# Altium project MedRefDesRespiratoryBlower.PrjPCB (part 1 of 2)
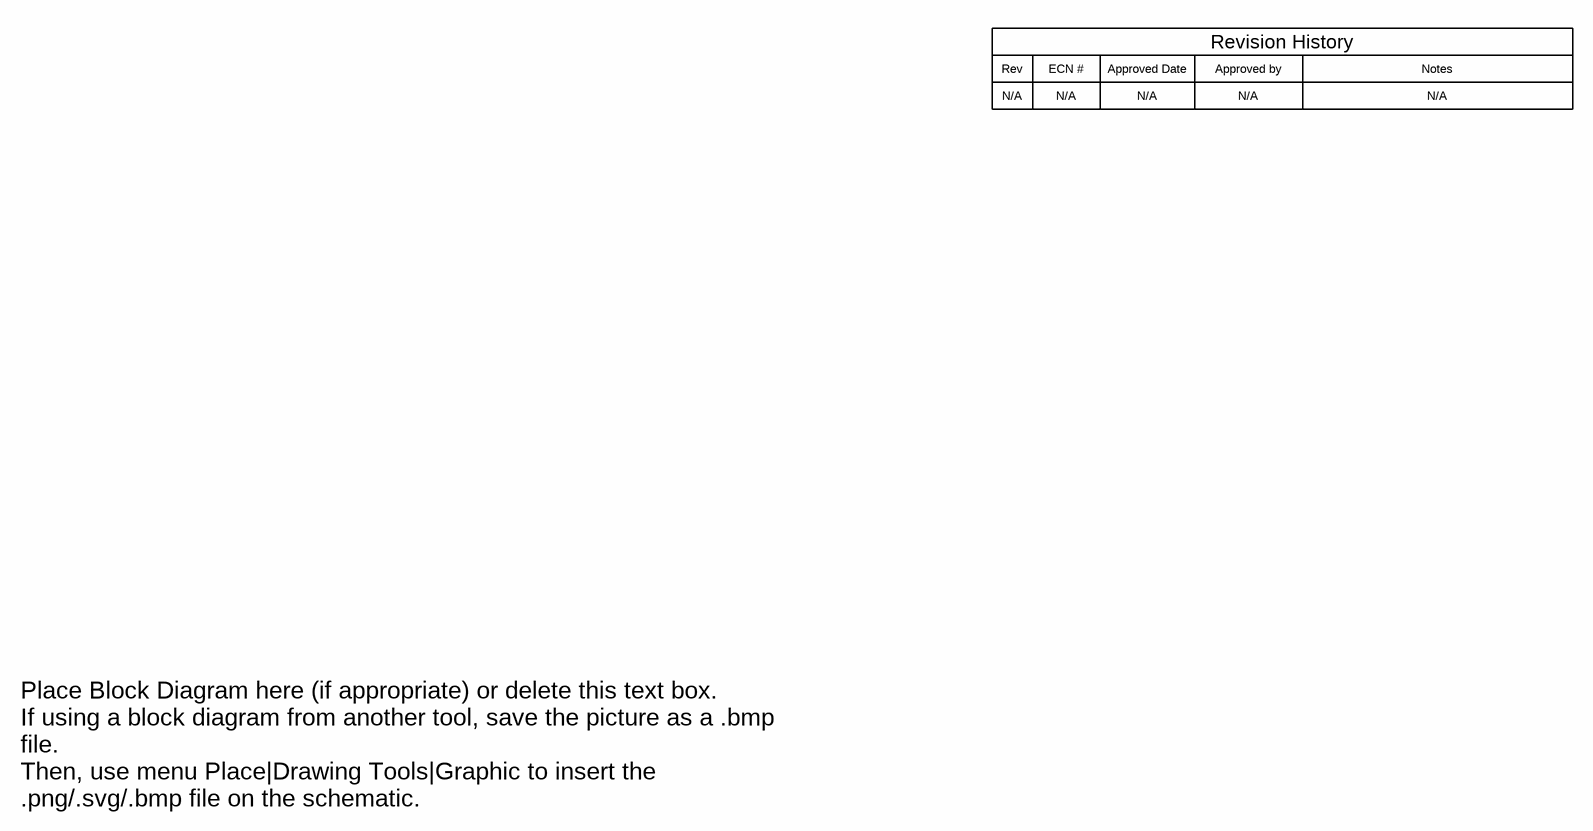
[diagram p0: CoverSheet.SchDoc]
TID: N/A; TechSupport: http://www.ti.com/support; SCH_Rev: E2; PRJ_Title: Change in menu Project|Project Options|Parameters; PRJ_Number: TIDA-010072; PRJ_Engineer: Kelvin Le; PRJ_Customer: Public Release; PCB_Rev: E2; CopyrightYear: 2020
6 sheets, 261 parts. Net scope: global (net labels, ports and power ports of the same name join across sheets).
Board file: Blower and Valve Board.PcbDoc
Sheets:
  CoverSheet.SchDoc
  Hardware.SchDoc
  BLDC Motor Driver and TMP Sensors.SchDoc
  MCU and Connectors.SchDoc
  Power Tree.SchDoc
  Valve Drivers and Fault Indicators.SchDoc

## Sheet CoverSheet.SchDoc
size 431 x 279 mm; Date: Not shown in title block; ApprovedBy: Not shown in title block; CheckedBy: Not shown in title block; Author: Not shown in title block; CompanyName: Not shown in title block; Engineer: Not shown in title block; Organization: Not shown in title block; Address1: Not shown in title block; Address2: Not shown in title block; Address3: Not shown in title block; Address4: Not shown in title block; DocumentNumber: 1; Revision: Use project parameter SCH_Rev; SheetNumber: 1; SheetTotal: 6; PageSetup: Record=PageOptions¦CenterHorizontal=True¦CenterVertical=True¦PrintScale=1.00¦XCorrection=1.00¦YCorrection=1.00¦PrintKind=0¦BorderSize=5000000¦LeftOffset=0¦BottomOffset=0¦Orientation=2¦PaperLength=1000¦PaperWidth=1000¦Scale=100¦PaperSource=15¦PrintQuality=600¦MediaType=1¦DitherType=10¦PaperKind=Letter¦PrintScaleMode=1

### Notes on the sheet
- Rev
- N/A
- ECN #
- Approved Date
- Approved by
- Revision History
- Notes
- Place Block Diagram here (if appropriate) or delete this text box.
  If using a block diagram from another tool, save the picture as a .bmp file.
  Then, use menu Place|Drawing Tools|Graphic to insert the .png/.svg/.bmp file on the schematic.

## Sheet Hardware.SchDoc
size 431 x 279 mm; Date: Not shown in title block; ApprovedBy: Not shown in title block; CheckedBy: Not shown in title block; Author: Not shown in title block; CompanyName: Not shown in title block; Engineer: Not shown in title block; Organization: Not shown in title block; Address1: Not shown in title block; Address2: Not shown in title block; Address3: Not shown in title block; Address4: Not shown in title block; DocumentNumber: 2; Revision: Use project parameter SCH_Rev; SheetNumber: 2; SheetTotal: 6; PageSetup: Record=PageOptions¦CenterHorizontal=True¦CenterVertical=True¦PrintScale=1.00¦XCorrection=1.00¦YCorrection=1.00¦PrintKind=0¦BorderSize=5000000¦LeftOffset=0¦BottomOffset=0¦Orientation=2¦PaperLength=1000¦PaperWidth=1000¦Scale=100¦PaperSource=15¦PrintQuality=600¦MediaType=1¦DitherType=10¦PaperKind=Letter¦PrintScaleMode=1
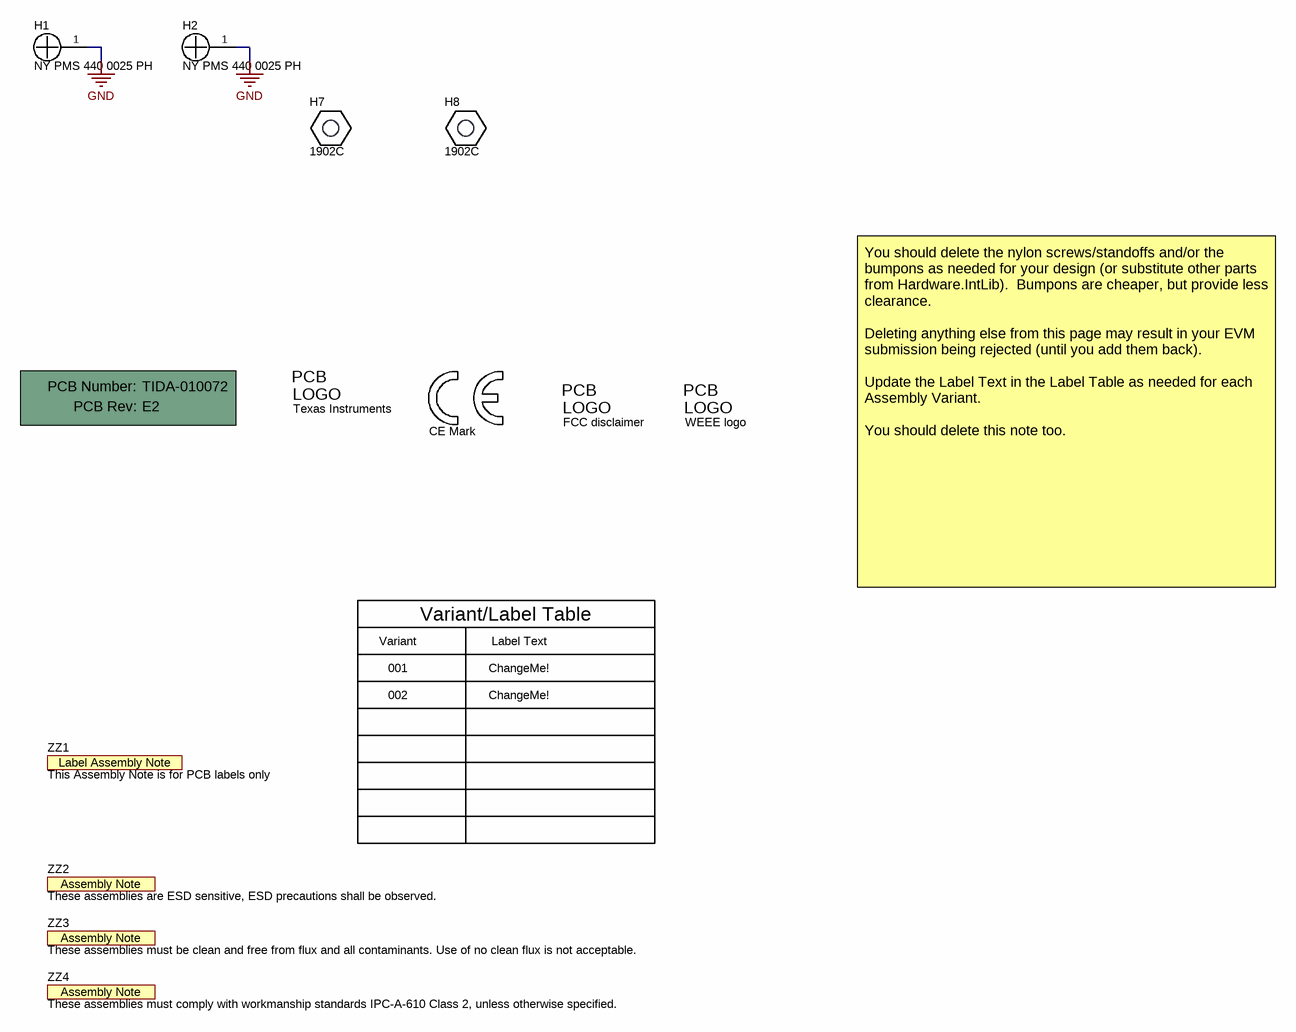
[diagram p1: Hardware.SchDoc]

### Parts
!PCB1  Printed Circuit Board  (value not drawn)  (mechanical)
H1  NY PMS 440 0025 PH  [NY PMS 440 0025 PH]
H2  NY PMS 440 0025 PH  [NY PMS 440 0025 PH]
H7  1902C  [Keystone_1902C]
H8  1902C  [Keystone_1902C]
Logo1  CE Mark  [CE_Mark_5mm]  (no BOM)
Logo2  Texas Instruments  [TI_Stacked_Overlay_Small]  (no BOM)
Logo3  FCC disclaimer  [FCC_disclaimer_stacked]  (no BOM)
Logo4  WEEE logo  [WEEE_Minimum]  (no BOM)
ZZ1  This Assembly Note is for PCB labels only  [AssemblyNoteLabel]  (no BOM)
ZZ2  These assemblies are ESD sensitive, ESD precautions shall be observed.  [AssemblyNote]  (no BOM)
ZZ3  These assemblies must be clean and free from flux and all contaminants. Use of no clean flux is not acceptable.  [AssemblyNote]  (no BOM)
ZZ4  These assemblies must comply with workmanship standards IPC-A-610 Class 2, unless otherwise specified.  [AssemblyNote]  (no BOM)

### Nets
GND: H1.1 H2.1

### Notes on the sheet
- Variant
- Variant/Label Table
- Label Text
- You should delete the nylon screws/standoffs and/or the bumpons as needed for your design (or substitute other parts from Hardware.IntLib).  Bumpons are cheaper, but provide less clearance.
  Deleting anything else from this page may result in your EVM submission being rejected (until you add them back).
  Update the Label Text in the Label Table as needed for each Assembly Variant.
  You should delete this note too.
- 001
- 002
- ChangeMe!

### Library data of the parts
!PCB1 = CMP-0003618-2: Manufacturer: Any; PartNumber: TIDA-010072
H1 H2 = CMP-0003617-1: Machine Screw, Round, #4-40 x 1/4, Nylon, Philips panhead; Manufacturer: B&F Fastener Supply; CompType: Hardware
H7 H8 = CMP-0003610-1: Standoff, Hex, 0.5"L #4-40 Nylon; Manufacturer: Keystone; CompType: Hardware
Logo1 = CMP-0074844-1: SymbolCreator: a0412235
Logo2 = CMP-0074838-1: Texas Instrument Corporate Signature; SymbolCreator: a0412235; Lib Reference: TI_Logo; Library Reference: Logo
Logo3 = CMP-0074847-1: FCC_disclaimer; Library Reference: Logo
Logo4 = CMP-0074769-1
ZZ1 = CMP-0003616-3
ZZ2 = CMP-0077236-1
ZZ3 = CMP-0077237-1
ZZ4 = CMP-0077238-1

## Sheet BLDC Motor Driver and TMP Sensors.SchDoc
size 431 x 279 mm; Date: Not shown in title block; ApprovedBy: Not shown in title block; CheckedBy: Not shown in title block; Author: Not shown in title block; CompanyName: Not shown in title block; Engineer: Not shown in title block; Organization: Not shown in title block; Address1: Not shown in title block; Address2: Not shown in title block; Address3: Not shown in title block; Address4: Not shown in title block; DocumentNumber: 2; Revision: Use project parameter SCH_Rev; SheetNumber: 2; SheetTotal: 3; PageSetup: Record=PageOptions¦CenterHorizontal=True¦CenterVertical=True¦PrintScale=1.00¦XCorrection=1.00¦YCorrection=1.00¦PrintKind=0¦BorderSize=5000000¦LeftOffset=0¦BottomOffset=0¦Orientation=2¦PaperLength=1000¦PaperWidth=1000¦Scale=100¦PaperSource=15¦PrintQuality=600¦MediaType=1¦DitherType=10¦PaperKind=Letter¦PrintScaleMode=1
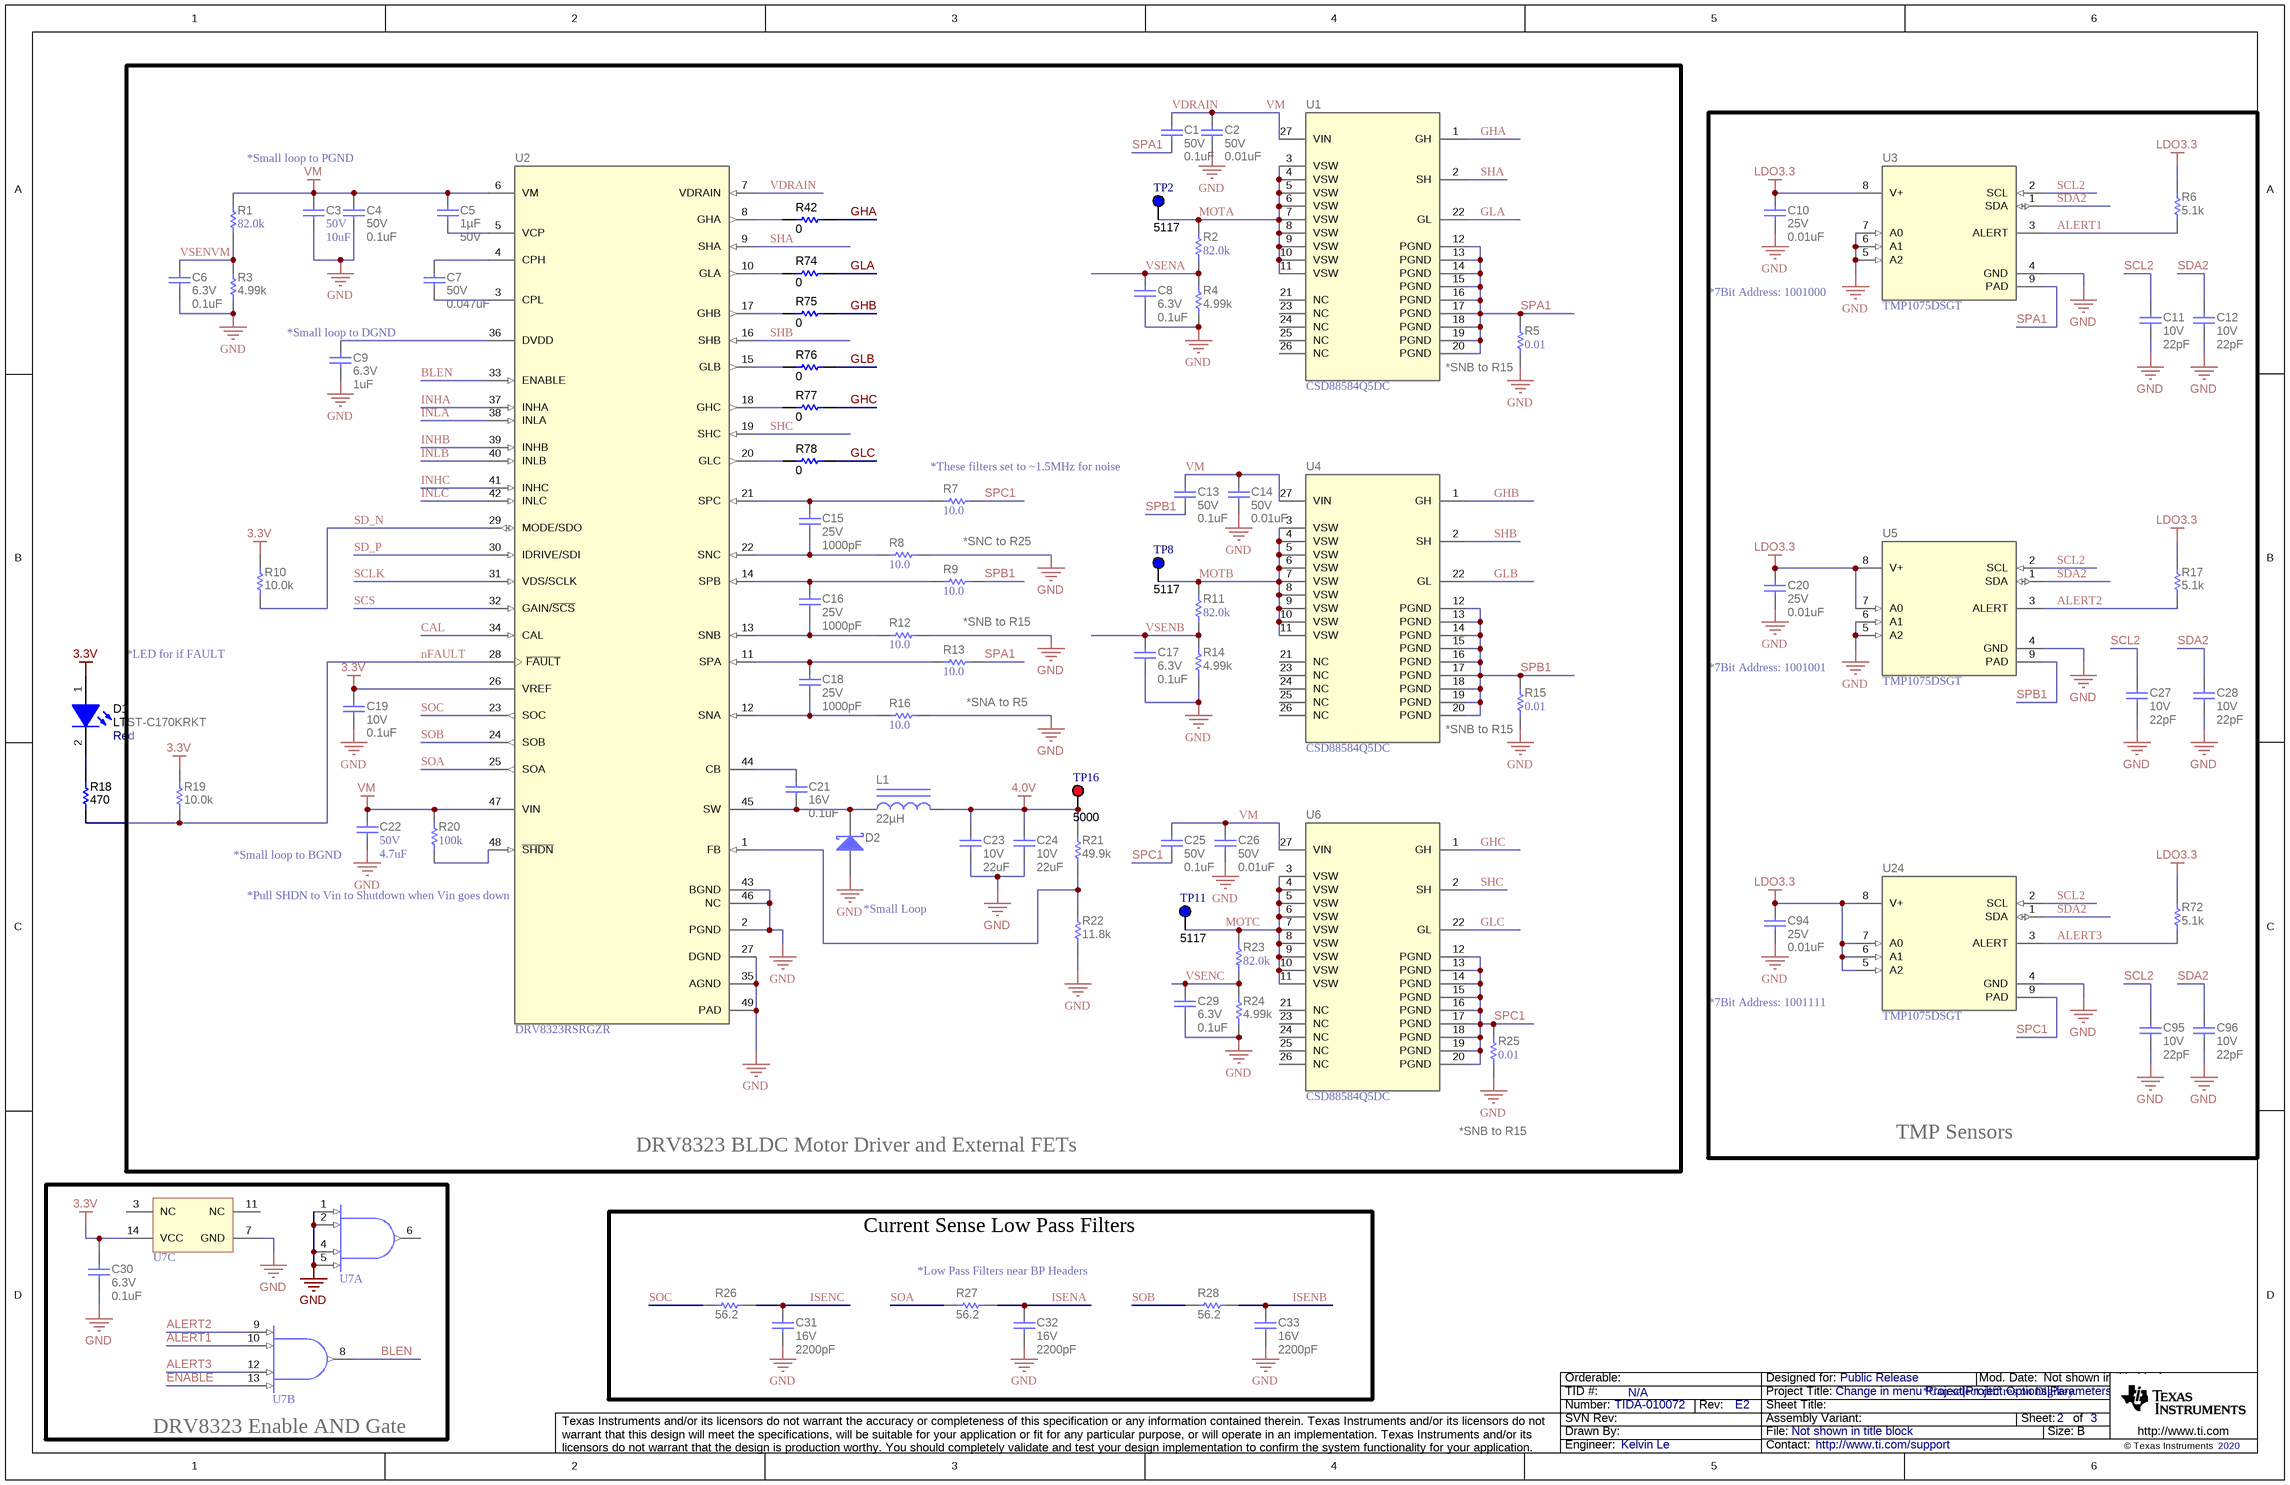
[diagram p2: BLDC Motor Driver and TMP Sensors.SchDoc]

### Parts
C1  VDC_V: 50V  ValueDisplayed: 0.1uF  [0402]  (hidden comment: C1005X7R1H104K050BB)
C2  VDC_V: 50V  ValueDisplayed: 0.01uF  [0402]  (hidden comment: GRM155R71H103KA88D)
C3  VDC_V: 50V  ValueDisplayed: 10uF  [1206_180]  (hidden comment: CL31B106KBHNNNE)
C4  VDC_V: 50V  ValueDisplayed: 0.1uF  [0402]  (hidden comment: C1005X7R1H104K050BB)
C5  Cap_F: 1µF  VDC_V: 50V  [0603]  (hidden comment: UMK107AB7105KA-T)
C6  VDC_V: 6.3V  ValueDisplayed: 0.1uF  [0402]  (hidden comment: 885012105001)
C7  VDC_V: 50V  ValueDisplayed: 0.047uF  [0402]  (hidden comment: C1005X7R1H473K050BB)
C8  VDC_V: 6.3V  ValueDisplayed: 0.1uF  [0402]  (hidden comment: 885012105001)
C9  VDC_V: 6.3V  ValueDisplayed: 1uF  [0402]  (hidden comment: GRM155R70J105MA12D)
C10  VDC_V: 25V  ValueDisplayed: 0.01uF  [0402]  (hidden comment: GRM155R71E103KA01D)
C11  VDC_V: 10V  ValueDisplayed: 22pF  [0402]  (hidden comment: 885012005009)
C12  VDC_V: 10V  ValueDisplayed: 22pF  [0402]  (hidden comment: 885012005009)
C13  VDC_V: 50V  ValueDisplayed: 0.1uF  [0402]  (hidden comment: C1005X7R1H104K050BB)
C14  VDC_V: 50V  ValueDisplayed: 0.01uF  [0402]  (hidden comment: GRM155R71H103KA88D)
C15  VDC_V: 25V  ValueDisplayed: 1000pF  [0402]  (hidden comment: GRM155R61E102KA01D)
C16  VDC_V: 25V  ValueDisplayed: 1000pF  [0402]  (hidden comment: GRM155R61E102KA01D)
C17  VDC_V: 6.3V  ValueDisplayed: 0.1uF  [0402]  (hidden comment: 885012105001)
C18  VDC_V: 25V  ValueDisplayed: 1000pF  [0402]  (hidden comment: GRM155R61E102KA01D)
C19  VDC_V: 10V  ValueDisplayed: 0.1uF  [0402]  (hidden comment: 885012105010)
C20  VDC_V: 25V  ValueDisplayed: 0.01uF  [0402]  (hidden comment: GRM155R71E103KA01D)
C21  VDC_V: 16V  ValueDisplayed: 0.1uF  [0402_065]  (hidden comment: 160R07X104KV4T)
C22  VDC_V: 50V  ValueDisplayed: 4.7uF  [0805_HV]  (hidden comment: C2012X5R1H475K125AB)
C23  VDC_V: 10V  ValueDisplayed: 22uF  [0603]  (hidden comment: C1608X5R1A226M080AC)
C24  VDC_V: 10V  ValueDisplayed: 22uF  [0603]  (hidden comment: C1608X5R1A226M080AC)
C25  VDC_V: 50V  ValueDisplayed: 0.1uF  [0402]  (hidden comment: C1005X7R1H104K050BB)
C26  VDC_V: 50V  ValueDisplayed: 0.01uF  [0402]  (hidden comment: GRM155R71H103KA88D)
C27  VDC_V: 10V  ValueDisplayed: 22pF  [0402]  (hidden comment: 885012005009)
C28  VDC_V: 10V  ValueDisplayed: 22pF  [0402]  (hidden comment: 885012005009)
C29  VDC_V: 6.3V  ValueDisplayed: 0.1uF  [0402]  (hidden comment: 885012105001)
C30  VDC_V: 6.3V  ValueDisplayed: 0.1uF  [0402]  (hidden comment: 885012105001)
C31  VDC_V: 16V  ValueDisplayed: 2200pF  [0402]  (hidden comment: GRM155R61C222KA01D)
C32  VDC_V: 16V  ValueDisplayed: 2200pF  [0402]  (hidden comment: GRM155R61C222KA01D)
C33  VDC_V: 16V  ValueDisplayed: 2200pF  [0402]  (hidden comment: GRM155R61C222KA01D)
C94  VDC_V: 25V  ValueDisplayed: 0.01uF  [0402]  (hidden comment: GRM155R71E103KA01D)
C95  VDC_V: 10V  ValueDisplayed: 22pF  [0402]  (hidden comment: 885012005009)
C96  VDC_V: 10V  ValueDisplayed: 22pF  [0402]  (hidden comment: 885012005009)
D1  LTST-C170KRKT  value Red  [LED_LTST-C170_Red]
D2  PMEG6010CEH,115  [SOD-123F]  (value not drawn)
L1  ValueDisplayed: 22µH  [WE-MAPI_4020]  (hidden comment: 74438356220)
R1  ValueDisplayed: 82.0k  [0402]  (hidden comment: RC0402FR-0782KL)
R2  ValueDisplayed: 82.0k  [0402]  (hidden comment: RC0402FR-0782KL)
R3  ValueDisplayed: 4.99k  [0402]  (hidden comment: CRCW04024K99FKED)
R4  ValueDisplayed: 4.99k  [0402]  (hidden comment: CRCW04024K99FKED)
R5  ValueDisplayed: 0.01  [2512]  (hidden comment: CRA2512-FZ-R010ELF)
R6  ValueDisplayed: 5.1k  [0402]  (hidden comment: CRCW04025K10JNED)
R7  ValueDisplayed: 10.0  [0402]  (hidden comment: RK73H1ETTP10R0F)
R8  ValueDisplayed: 10.0  [0402]  (hidden comment: RK73H1ETTP10R0F)
R9  ValueDisplayed: 10.0  [0402]  (hidden comment: RK73H1ETTP10R0F)
R10  ValueDisplayed: 10.0k  [0402]  (hidden comment: CRCW040210K0FKED)
R11  ValueDisplayed: 82.0k  [0402]  (hidden comment: RC0402FR-0782KL)
R12  ValueDisplayed: 10.0  [0402]  (hidden comment: RK73H1ETTP10R0F)
R13  ValueDisplayed: 10.0  [0402]  (hidden comment: RK73H1ETTP10R0F)
R14  ValueDisplayed: 4.99k  [0402]  (hidden comment: CRCW04024K99FKED)
R15  ValueDisplayed: 0.01  [2512]  (hidden comment: CRA2512-FZ-R010ELF)
R16  ValueDisplayed: 10.0  [0402]  (hidden comment: RK73H1ETTP10R0F)
R17  ValueDisplayed: 5.1k  [0402]  (hidden comment: CRCW04025K10JNED)
R18  ValueDisplayed: 470  [0402]  (hidden comment: CRCW0402470RJNED)
R19  ValueDisplayed: 10.0k  [0402]  (hidden comment: CRCW040210K0FKED)
R20  ValueDisplayed: 100k  [0402]  (hidden comment: RMCF0402FT100K)
R21  ValueDisplayed: 49.9k  [0402]  (hidden comment: CRCW040249K9FKED)
R22  ValueDisplayed: 11.8k  [0402]  (hidden comment: CRCW040211K8FKED)
R23  ValueDisplayed: 82.0k  [0402]  (hidden comment: RC0402FR-0782KL)
R24  ValueDisplayed: 4.99k  [0402]  (hidden comment: CRCW04024K99FKED)
R25  ValueDisplayed: 0.01  [2512]  (hidden comment: CRA2512-FZ-R010ELF)
R26  ValueDisplayed: 56.2  [0402]  (hidden comment: CRCW040256R2FKED)
R27  ValueDisplayed: 56.2  [0402]  (hidden comment: CRCW040256R2FKED)
R28  ValueDisplayed: 56.2  [0402]  (hidden comment: CRCW040256R2FKED)
R42  ValueDisplayed: 0  [0402]  (hidden comment: CRCW04020000Z0EDHP)
R72  ValueDisplayed: 5.1k  [0402]  (hidden comment: CRCW04025K10JNED)
R74  ValueDisplayed: 0  [0402]  (hidden comment: CRCW04020000Z0EDHP)
R75  ValueDisplayed: 0  [0402]  (hidden comment: CRCW04020000Z0EDHP)
R76  ValueDisplayed: 0  [0402]  (hidden comment: CRCW04020000Z0EDHP)
R77  ValueDisplayed: 0  [0402]  (hidden comment: CRCW04020000Z0EDHP)
R78  ValueDisplayed: 0  [0402]  (hidden comment: CRCW04020000Z0EDHP)
TP2  5117  [Keystone5117]
TP8  5117  [Keystone5117]
TP11  5117  [Keystone5117]
TP16  5000  [Keystone5000]
U1  CSD88584Q5DC  [DMM0022A]
U2  DRV8323RSRGZR  [RGZ0048A]
U3  TMP1075DSGT  [DSG0008A]
U4  CSD88584Q5DC  [DMM0022A]
U5  TMP1075DSGT  [DSG0008A]
U6  CSD88584Q5DC  [DMM0022A]
U7  SN74HC21PW  [PW0014A_N]  (value not drawn)  (parts A,B,C of 3)
U24  TMP1075DSGT  [DSG0008A]

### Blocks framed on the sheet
DRV8323 BLDC Motor Driver and External FETs: C1-C9 C13-C19 C21-C26 C29 D2 L1 R1-R5 R7-R16 R19-R25 R42 R74-R78 TP2 TP8 TP11 TP16 U1 U2 U4 U6
TMP Sensors: C10-C12 C20 C27 C28 C94-C96 R6 R17 R72 U3 U5 U24
DRV8323 Enable AND Gate: C30 U7
Current Sense Low Pass Filters: C31-C33 R26-R28

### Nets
3.3V: C19.1 C30.1 D1.1(A) R10.2 R19.2 U2.26(VREF) U7.14(VCC)
4.0V: C23.1 C24.1 L1.2 R21.2 TP16.1
GND: C2.2 C3.2 C4.2 C6.2 C8.2 C9.2 C10.2 C11.2 C12.2 C14.2 C17.2 C19.2 C20.2 C22.2 C23.2 C24.2 C26.2 C27.2 C28.2 C29.2 C30.2 C31.2 C32.2 C33.2 C94.2 C95.2 C96.2 D2.2(A) R3.1 R4.1 R5.1 R8.1 R12.1 R14.1 R15.1 R16.1 R22.1 R24.1 R25.1 U2.2(PGND) U2.27(DGND) U2.35(AGND) U2.43(BGND) U2.46(NC) U2.49(PAD) U3.4(GND) U3.5(A2) U3.6(A1) U3.7(A0) U5.4(GND) U5.5(A2) U5.6(A1) U7.1(1A) U7.2(1B) U7.4(1C) U7.5(1D) U7.7(GND) U24.4(GND)
LDO3.3: C10.1 C20.1 C94.1 R6.2 R17.2 R72.2 U3.8(V+) U5.7(A0) U5.8(V+) U24.5(A2) U24.6(A1) U24.7(A0) U24.8(V+)
VDRAIN: C1.1 C2.1 C3.1 C4.1 C5.1 C13.1 C14.1 C22.1 C25.1 C26.1 R1.2 R20.2 U1.27(VIN) U2.6(VM) U2.7(VDRAIN) U2.47(VIN) U4.27(VIN) U6.27(VIN)  [also labelled VM]
ALERT1: R6.1 U3.3(ALERT) U7.10(2B)
ALERT2: R17.1 U5.3(ALERT) U7.9(2A)
ALERT3: R72.1 U7.12(2C) U24.3(ALERT)
BLEN: U2.33(ENABLE) U7.8(2Y)
CAL: U2.34(CAL)
ENABLE: U7.13(2D)
GHA: R42.2 U1.1(GH)
GHB: R75.2 U4.1(GH)
GHC: R77.2 U6.1(GH)
GLA: R74.2 U1.22(GL)
GLB: R76.2 U4.22(GL)
GLC: R78.2 U6.22(GL)
INHA: U2.37(INHA)
INHB: U2.39(INHB)
INHC: U2.41(INHC)
INLA: U2.38(INLA)
INLB: U2.40(INLB)
INLC: U2.42(INLC)
ISENA: C32.1 R27.2
ISENB: C33.1 R28.2
ISENC: C31.1 R26.2
MOTA: R2.2 TP2.1 U1.3(VSW) U1.4(VSW) U1.5(VSW) U1.6(VSW) U1.7(VSW) U1.8(VSW) U1.9(VSW) U1.10(VSW) U1.11(VSW)
MOTB: R11.2 TP8.1 U4.3(VSW) U4.4(VSW) U4.5(VSW) U4.6(VSW) U4.7(VSW) U4.8(VSW) U4.9(VSW) U4.10(VSW) U4.11(VSW)
MOTC: R23.2 TP11.1 U6.3(VSW) U6.4(VSW) U6.5(VSW) U6.6(VSW) U6.7(VSW) U6.8(VSW) U6.9(VSW) U6.10(VSW) U6.11(VSW)
nFAULT: R18.1 R19.1 U2.28(~{FAULT})
SCL2: C11.1 C27.1 C95.1 U3.2(SCL) U5.2(SCL) U24.2(SCL)
SCLK: U2.31(VDS/SCLK)
SCS: U2.32(GAIN/~{SCS})
SD_N: R10.1 U2.29(MODE/SDO)
SD_P: U2.30(IDRIVE/SDI)
SDA2: C12.1 C28.1 C96.1 U3.1(SDA) U5.1(SDA) U24.1(SDA)
SHA: U1.2(SH) U2.9(SHA)
SHB: U2.16(SHB) U4.2(SH)
SHC: U2.19(SHC) U6.2(SH)
SOA: R27.1 U2.25(SOA)
SOB: R28.1 U2.24(SOB)
SOC: R26.1 U2.23(SOC)
SPA1: C1.2 R5.2 R13.1 U1.12(PGND) U1.13(PGND) U1.14(PGND) U1.15(PGND) U1.16(PGND) U1.17(PGND) U1.18(PGND) U1.19(PGND) U1.20(PGND) U3.9(PAD)
SPB1: C13.2 R9.1 R15.2 U4.12(PGND) U4.13(PGND) U4.14(PGND) U4.15(PGND) U4.16(PGND) U4.17(PGND) U4.18(PGND) U4.19(PGND) U4.20(PGND) U5.9(PAD)
SPC1: C25.2 R7.1 R25.2 U6.12(PGND) U6.13(PGND) U6.14(PGND) U6.15(PGND) U6.16(PGND) U6.17(PGND) U6.18(PGND) U6.19(PGND) U6.20(PGND) U24.9(PAD)
VSENA: C8.1 R2.1 R4.2
VSENB: C17.1 R11.1 R14.2
VSENC: C29.1 R23.1 R24.2
VSENVM: C6.1 R1.1 R3.2
NetC5_2: C5.2 U2.5(VCP)
NetC7_1: C7.1 U2.4(CPH)
NetC7_2: C7.2 U2.3(CPL)
NetC9_1: C9.1 U2.36(DVDD)
NetC15_1: C15.1 R7.2 U2.21(SPC)
NetC15_2: C15.2 R8.2 U2.22(SNC)
NetC16_1: C16.1 R9.2 U2.14(SPB)
NetC16_2: C16.2 R12.2 U2.13(SNB)
NetC18_1: C18.1 R13.2 U2.11(SPA)
NetC18_2: C18.2 R16.2 U2.12(SNA)
NetC21_1: C21.1 U2.44(CB)
NetC21_2: C21.2 D2.1(K) L1.1 U2.45(SW)
NetD1_2: D1.2(K) R18.2
NetR20_1: R20.1 U2.48(~{SHDN})
NetR21_1: R21.1 R22.2 U2.1(FB)
NetR42_1: R42.1 U2.8(GHA)
NetR74_1: R74.1 U2.10(GLA)
NetR75_1: R75.1 U2.17(GHB)
NetR76_1: R76.1 U2.15(GLB)
NetR77_1: R77.1 U2.18(GHC)
NetR78_1: R78.1 U2.20(GLC)

Not connected (* = marked no-connect by the designer): U1 21(NC) 23(NC) 24(NC) 25(NC) 26(NC); U4 21(NC) 23(NC) 24(NC) 25(NC) 26(NC); U6 21(NC) 23(NC) 24(NC) 25(NC) 26(NC); U7 3(NC) 6(1Y) 11(NC)

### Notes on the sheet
- *Small loop to PGND
- (near U3) *7Bit Address: 1001000
- (near C9) *Small loop to DGND
- *SNB to R15
- *These filters set to
  .5MHz for noise
- *SNC to R25
- *LED for if FAULT
- *SNA to R5
- (near U5) *7Bit Address: 1001001
- (near C22) *Small loop to BGND
- (near U2) *Pull SHDN to Vin to Shutdown when Vin goes down
- *Small Loop
- (near U24) *7Bit Address: 1001111
- *Low Pass Filters near BP Headers
- *Can select diff res on Digikey

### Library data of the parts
C1 C4 C13 C25 = CMP-0006297-2: CAP, CERM, 0.1 uF, 50 V, +/- 10%, X7R, 0402; Manufacturer: TDK; TaMin_C: -55°C; ESR_ohm: 0.039064; Polarized: N; SizeAreaWB_mm2: 3; Value1: 0.039064 ohm; U/M: EA; Value: 0.1uF; TaMax_C: 125°C; SizeZ_mm: 0.6; SizeX_mm: 1; SizeY_mm: 0.5; Cap_F: 100nF; IRMS_A: 814.669mA; AEC Category: Q200
C2 C14 C26 = CMP-0006674-2: CAP, CERM, 0.01 uF, 50 V, +/- 10%, X7R, 0402; Manufacturer: MuRata; TaMin_C: -55°C; Polarized: N; SizeAreaWB_mm2: 3; Value1: Unknown; U/M: EA; Value: 0.01uF; TaMax_C: 125°C; SizeZ_mm: 0.6; SizeX_mm: 1; SizeY_mm: 0.5; Cap_F: 10nF; AEC Category: Q200
C3 = CMP-0008802-2: CAP, CERM, 10 uF, 50 V, +/- 10%, X7R, 1206; Manufacturer: Samsung; TaMin_C: -55°C; Polarized: N; SizeAreaWB_mm2: 10.92; Value1: Unknown; U/M: EA; Value: 10uF; TaMax_C: 125°C; SizeZ_mm: 1.8; SizeX_mm: 3.2; SizeY_mm: 1.6; Cap_Case: 1206; SizeArea_mm2: 5.12; Cap_F: 10µF; AEC Category: Q200
C5 = CMP-0007508-5: CAP, CERM, 1 uF, 50 V, +/- 10%, X7R, 0603; Manufacturer: Taiyo Yuden; TaMin_C: -55°C; Polarized: N; SizeAreaWB_mm2: 4.68; Value1: Unknown; U/M: EA; Value: 1uF; TaMax_C: 125°C; SizeZ_mm: 1; SizeX_mm: 1.6; SizeY_mm: 0.8; SizeArea_mm2: 1.28; AEC Category: Q200
C6 C8 C17 C29 C30 = CMP-0006219-2: CAP, CERM, 0.1 uF, 6.3 V, +/- 20%, X5R, 0402; Manufacturer: Wurth Elektronik; TaMin_C: -55°C; Polarized: N; SizeAreaWB_mm2: 3; Value1: Unknown; U/M: EA; Value: 0.1uF; TaMax_C: 85°C; SizeZ_mm: 0.6; SizeX_mm: 1; SizeY_mm: 0.5; Cap_F: 100nF; AEC Category: Q200
C7 = CMP-0006298-2: CAP, CERM, 0.047 uF, 50 V, +/- 10%, X7R, 0402; Manufacturer: TDK; TaMin_C: -55°C; ESR_ohm: 0.06407; Polarized: N; SizeAreaWB_mm2: 3; Value1: 0.06407 ohm; U/M: EA; SizeZ_mm: 0.6; SizeX_mm: 1; SizeY_mm: 0.5; Cap_F: 47nF; IRMS_A: 646.122mA; AEC Category: Q200; TaMax_C: 125°C
C9 = CMP-0006624-2: CAP, CERM, 1 uF, 6.3 V, +/- 20%, X7R, 0402; Manufacturer: MuRata; TaMin_C: -55°C; Polarized: N; SizeAreaWB_mm2: 3; Value1: Unknown; U/M: EA; Value: 1uF; TaMax_C: 125°C; SizeZ_mm: 0.6; SizeX_mm: 1; SizeY_mm: 0.5; Cap_F: 1µF; AEC Category: Q200
C10 C20 C94 = CMP-0006658-2: CAP, CERM, 0.01 uF, 25 V, +/- 10%, X7R, 0402; Manufacturer: MuRata; TaMin_C: -55°C; Polarized: N; SizeAreaWB_mm2: 3; Value1: Unknown; U/M: EA; Value: 0.01uF; TaMax_C: 125°C; SizeZ_mm: 0.6; SizeX_mm: 1; SizeY_mm: 0.5; Cap_F: 10nF; AEC Category: Q200
C11 C12 C27 C28 C95 C96 = CMP-0064912-2: CAP, CERM, 22 pF, 10 V,+/- 5%, C0G/NP0, 0402; Manufacturer: Wurth Elektronik; TaMin_C: -55°C; Polarized: N; SizeAreaWB_mm2: 3; Value1: Unknown; U/M: EA; Value: 22pF; TaMax_C: 125°C; SizeZ_mm: 0.6; SizeX_mm: 1; SizeY_mm: 0.5; AEC Category: Q200
C15 C16 C18 = CMP-0006606-2: CAP, CERM, 1000 pF, 25 V, +/- 10%, X5R, 0402; Manufacturer: MuRata; TaMin_C: -55°C; Polarized: N; SizeAreaWB_mm2: 3; Value1: Unknown; U/M: EA; Value: 1000pF; TaMax_C: 85°C; SizeZ_mm: 0.6; SizeX_mm: 1; SizeY_mm: 0.5; Cap_F: 1nF; AEC Category: Q200
C19 = CMP-0006221-2: CAP, CERM, 0.1 uF, 10 V, +/- 20%, X5R, 0402; Manufacturer: Wurth Elektronik; TaMin_C: -55°C; Polarized: N; SizeAreaWB_mm2: 3; Value1: Unknown; U/M: EA; Value: 0.1uF; TaMax_C: 85°C; SizeZ_mm: 0.6; SizeX_mm: 1; SizeY_mm: 0.5; Cap_F: 100nF; AEC Category: Q200
C21 = CMP-0006204-2: CAP, CERM, 0.1 uF, 16 V, +/- 10%, X5R, 0402; Manufacturer: Johanson Technology; TaMin_C: -55°C; Polarized: N; SizeAreaWB_mm2: 3; Value1: Unknown; U/M: EA; Value: 0.1uF; TaMax_C: 85°C; SizeZ_mm: 0.65; SizeX_mm: 1; SizeY_mm: 0.5; Cap_Case: 0402; Cap_F: 100nF; AEC Category: Q200
C22 = CMP-0007840-2: CAP, CERM, 4.7 uF, 50 V, +/- 10%, X5R, 0805; Manufacturer: TDK; TaMin_C: -55°C; ESR_ohm: 2.346m; Polarized: N; SizeAreaWB_mm2: 6.75; Value1: 0.002346 ohm; U/M: EA; Value: 4.7uF; TaMax_C: 85°C; SizeZ_mm: 1.45; SizeX_mm: 2; SizeY_mm: 1.25; Cap_Case: 0805; SizeArea_mm2: 2.5; Cap_F: 4.7µF; IRMS_A: 4.26021A; AEC Category: Q200
C23 C24 = CMP-0007005-5: CAP, CERM, 22 uF, 10 V, +/- 20%, X5R, 0603; Manufacturer: TDK; TaMin_C: -55°C; ESR_ohm: 3.71m; Polarized: N; SizeAreaWB_mm2: 4.68; Value1: 0.00371 ohm; U/M: EA; Value: 22uF; TaMax_C: 85°C; SizeZ_mm: 1; SizeX_mm: 1.6; SizeY_mm: 0.8; SizeArea_mm2: 1.28; Cap_F: 22µF; IRMS_A: 2.69936A; AEC Category: Q200
C31-C33 = CMP-0006592-2: CAP, CERM, 2200 pF, 16 V, +/- 10%, X5R, 0402; Manufacturer: MuRata; TaMin_C: -55°C; Polarized: N; SizeAreaWB_mm2: 3; Value1: Unknown; U/M: EA; Value: 2200pF; TaMax_C: 85°C; SizeZ_mm: 0.6; SizeX_mm: 1; SizeY_mm: 0.5; Cap_F: 2.2nF; AEC Category: Q200
D1 = CMP-0002829-3: LED, Red, SMD; Manufacturer: Lite-On; Io_A: 20mA; SizeAreaWB_mm2: 6.75; Value1: W; SizeZ_mm: 1.2; SizeX_mm: 2; SizeY_mm: 1.25; Vf_V: 2V; SizeArea_mm2: 2.5; Type: AlInGaP
D2 = CMP-0028377-2: Diode, Schottky, 60 V, 1 A, SOD-123F; Manufacturer: Nexperia; Value1: 1A; Value2: 0.57V; TJmax_C: 150°C; Green_REACh: Incomplete; Vr_V: 60V; SizeY_mm: 1.6; Vf_V: 570mV; SizeArea_mm2: 5.6; AEC Category: Q101; SizeZ_mm: 1.1; SizeX_mm: 3.5; Value: 60V; Green_Lifecycle: Not Set; SizeAreaWB_mm2: 11.7
L1 = CMP-0082329-1: Inductor, Shielded, 22 µH, 1.7 A, 0.28 ohm, SMD; Manufacturer: Wurth Elektronik; SizeAreaWB_mm2: 26.01; Irms: 1.7A @ 40C rise; SizeArea_mm2: 16.81; AEC Qualified: N; AEC Category: Q200; Value: 22uH; SizeZ_mm: 2.1; Imax_A: 1.7A; SizeY_mm: 4.1; Isat: 1.85A @ 20% inductance drop; DCR_ohm: 0.28
R1 R2 R11 R23 = CMP-0026744-1: RES, 82.0 k, 1%, 0.063 W, 0402; Manufacturer: Yageo America; Power_W: 63mW; TempCo: 100 ppm/C; Value_Code: 82k0; U/M: EA; Value: 82.0k; Res_ohm: 82k; SizeX_mm: 1; SizeY_mm: 0.5; SizeZ_mm: 0.6; Value2: 0.063W; AEC Qualified: N; VDC_V: 50V; AEC Category: Q200
R3 R4 R14 R24 = CMP-0026414-2: RES, 4.99 k, 1%, 0.063 W, AEC-Q200 Grade 0, 0402; Manufacturer: Vishay-Dale; Power_W: 63mW; TempCo: 100 ppm/C; Value_Code: 4k99; Value: 4.99k; EIA_Code: E96; SizeX_mm: 1; SizeY_mm: 0.5; SizeZ_mm: 0.6; Value2: 0.063W; AEC Qualified: Y; VDC_V: 50V; AEC Category: Q200; AEC Grade: 0
R5 R15 R25 = CMP-0015418-2: RES, 0.01, 1%, 3 W, 2512; Manufacturer: Bourns; Power_W: 3W; TempCo: 75 ppm/C; Value_Code: R010; U/M: EA; Value: 0.01; EIA_Code: E96; SizeX_mm: 6.3; SizeY_mm: 3.2; SizeZ_mm: 0.71; SizeArea_mm2: 20.16; AEC Category: Q200
R6 R17 R72 = CMP-0026951-5: RES, 5.1 k, 5%, 0.063 W, AEC-Q200 Grade 0, 0402; Manufacturer: Vishay-Dale; Power_W: 63mW; TempCo: 200 ppm/C; Value_Code: 5k10; Value: 5.1k; EIA_Code: E24; SizeX_mm: 1; SizeY_mm: 0.5; SizeZ_mm: 0.6; Value2: 0.063W; AEC Qualified: Y; VDC_V: 50V; AEC Category: Q200; AEC Grade: 0
R7-R9 R12 R13 R16 = CMP-0026749-1: RES, 10.0, 1%, 0.063 W, 0402; Manufacturer: KOA Speer; Power_W: 63mW; TempCo: 100 ppm/C; Value_Code: 10R0; U/M: EA; Value: 10.0; EIA_Code: E96; Res_ohm: 10; SizeX_mm: 1; SizeY_mm: 0.5; SizeZ_mm: 0.6; Value2: 0.063W; AEC Qualified: N; VDC_V: 50V; AEC Category: Q200
R10 R19 = CMP-0025958-3: RES, 10.0 k, 1%, 0.063 W, AEC-Q200 Grade 0, 0402; Manufacturer: Vishay-Dale; Power_W: 63mW; TempCo: 100 ppm/C; Value_Code: 10k0; Value: 10.0k; EIA_Code: E96; Res_ohm: 10k; SizeX_mm: 1; SizeY_mm: 0.5; SizeZ_mm: 0.6; Value2: 0.063W; AEC Qualified: Y; VDC_V: 50V; AEC Category: Q200; AEC Grade: 0
R18 = CMP-0026934-3: RES, 470, 5%, 0.063 W, AEC-Q200 Grade 0, 0402; Manufacturer: Vishay-Dale; Power_W: 63mW; TempCo: 200 ppm/C; Value_Code: 470R; Value: 470; EIA_Code: E24; SizeX_mm: 1; SizeY_mm: 0.5; SizeZ_mm: 0.6; Value2: 0.063W; AEC Qualified: Y; VDC_V: 50V; AEC Category: Q200; AEC Grade: 0
R20 = CMP-0026753-1: RES, 100 k, 1%, 0.063 W, AEC-Q200 Grade 0, 0402; Manufacturer: Stackpole Electronics Inc; Power_W: 63mW; TempCo: 100 ppm/C; U/M: EA; Value: 100k; EIA_Code: E96; SizeX_mm: 1; SizeY_mm: 0.5; SizeZ_mm: 0.6; Value2: 0.063W; AEC Qualified: Y; VDC_V: 50V; AEC Grade: 0; AEC Category: Q200
R21 = CMP-0026403-2: RES, 49.9 k, 1%, 0.063 W, AEC-Q200 Grade 0, 0402; Manufacturer: Vishay-Dale; Power_W: 63mW; TempCo: 100 ppm/C; Value_Code: 49k9; Value: 49.9k; EIA_Code: E96; SizeX_mm: 1; SizeY_mm: 0.5; SizeZ_mm: 0.6; Value2: 0.063W; AEC Qualified: Y; VDC_V: 50V; AEC Category: Q200; AEC Grade: 0
R22 = CMP-0025978-3: RES, 11.8 k, 1%, 0.063 W, AEC-Q200 Grade 0, 0402; Manufacturer: Vishay-Dale; Power_W: 63mW; TempCo: 100 ppm/C; Value_Code: 11k8; Value: 11.8k; EIA_Code: E96; SizeX_mm: 1; SizeY_mm: 0.5; SizeZ_mm: 0.6; Value2: 0.063W; AEC Qualified: Y; VDC_V: 50V; AEC Category: Q200; AEC Grade: 0
R26-R28 = CMP-0026454-2: RES, 56.2, 1%, 0.063 W, AEC-Q200 Grade 0, 0402; Manufacturer: Vishay-Dale; Power_W: 63mW; TempCo: 100 ppm/C; Value_Code: 56R2; Value: 56.2; EIA_Code: E96; SizeX_mm: 1; SizeY_mm: 0.5; SizeZ_mm: 0.6; Value2: 0.063W; AEC Qualified: Y; VDC_V: 50V; AEC Category: Q200; AEC Grade: 0
R42 R74-R78 = CMP-0081856-1: RES, 0, 0%, 0.2 W, AEC-Q200 Grade 0, 0402; Manufacturer: Vishay-Dale; SizeAreaWB_mm2: 3; SizeArea_mm2: 0.5; AEC Qualified: Y; AEC Category: Q200; Value: 0; SizeZ_mm: 0.6; Power_W: 200mW; VDC_V: 50V; Value2: 0.2W; SizeX_mm: 1
TP2 TP8 TP11 = CMP-0055154-1: Test Point, Miniature, Blue, TH; Manufacturer: Keystone; CNHeader: FALSE; Green_Lifecycle: Active; Green_REACh: Passed; ContactFinish: Silver; CT: TRUE
TP16 = CMP-0055137-1: Test Point, Miniature, Red, TH; Manufacturer: Keystone; CNHeader: FALSE; Green_Lifecycle: Active; Green_REACh: Passed; ContactFinish: Silver; CT: TRUE
U1 U4 U6 = CMP-0013348-3: 40 V Half-Bridge NexFE Power Block, DMM0022A (LSON-CLIP-27); Manufacturer: Texas Instruments; Alternate PartNumber: CSD88584Q5DCT; SizeX_mm: 5; SizeY_mm: 6; CompType: IC; SizeZ_mm: 1.05; SizeArea_mm2: 30; SizeAreaWB_mm2: 56; U/M: EA; AEC Category: Q200; AEC Qualified: N
U2 = CMP-0013777-5: 60V Three-Phase Smart Gate Driver With Buck Regulator and Three Current Shunt Amplifiers, RGZ0048A (VQFN-48); Alternate PartNumber: DRV8323RSRGZT; Manufacturer: Texas Instruments; CompType: IC; SizeX_mm: 7; AEC Qualified: N; SizeZ_mm: 1; SizeArea_mm2: 49; SizeAreaWB_mm2: 81; Rating: Catalog; AEC Category: Q200
U3 U5 U24 = CMP-0081592-2: I2C Compatible Upgrade to Industry Standard LM75 / TMP75 Digital Temperature Sensors, DSG0008A (WSON-8); Alternate PartNumber: TMP1075DSGR; Alternate Manufacturer: Texas Instruments; SizeAreaWB_mm2: 9; Rating: Catalog; SizeZ_mm: 0.8; SizeX_mm: 2; SizeArea_mm2: 4; CompType: IC; AEC Qualified: N; AEC Category: Q200
U7 = CMP-0054473-1: Dual 4-Input Positive-AND Gates, PW0014A, TUBE; Manufacturer: Texas Instruments; Schmitt Trigger: No; VCC(Min)(V): 2; ICC @ Nom Voltage(Max)(mA): 0.02; Voltage(Nom)(V): 5; Technology Family: HC; F @ Nom Voltage(Max)(Mhz): 70; Output Type: CMOS; Rating: Catalog; tpd @ Nom Voltage(Max)(ns): 28; VCC(Max)(V): 6

## Sheet MCU and Connectors.SchDoc
size 431 x 279 mm; Date: Not shown in title block; ApprovedBy: Not shown in title block; CheckedBy: Not shown in title block; Author: Not shown in title block; CompanyName: Not shown in title block; Engineer: Not shown in title block; Organization: Not shown in title block; Address1: Not shown in title block; Address2: Not shown in title block; Address3: Not shown in title block; Address4: Not shown in title block; DocumentNumber: 4; Revision: Use project parameter SCH_Rev; SheetNumber: 4; SheetTotal: 6; PageSetup: Record=PageOptions¦CenterHorizontal=True¦CenterVertical=True¦PrintScale=1.00¦XCorrection=1.00¦YCorrection=1.00¦PrintKind=0¦BorderSize=5000000¦LeftOffset=0¦BottomOffset=0¦Orientation=2¦PaperLength=1000¦PaperWidth=1000¦Scale=100¦PaperSource=15¦PrintQuality=600¦MediaType=1¦DitherType=10¦PaperKind=Letter¦PrintScaleMode=1
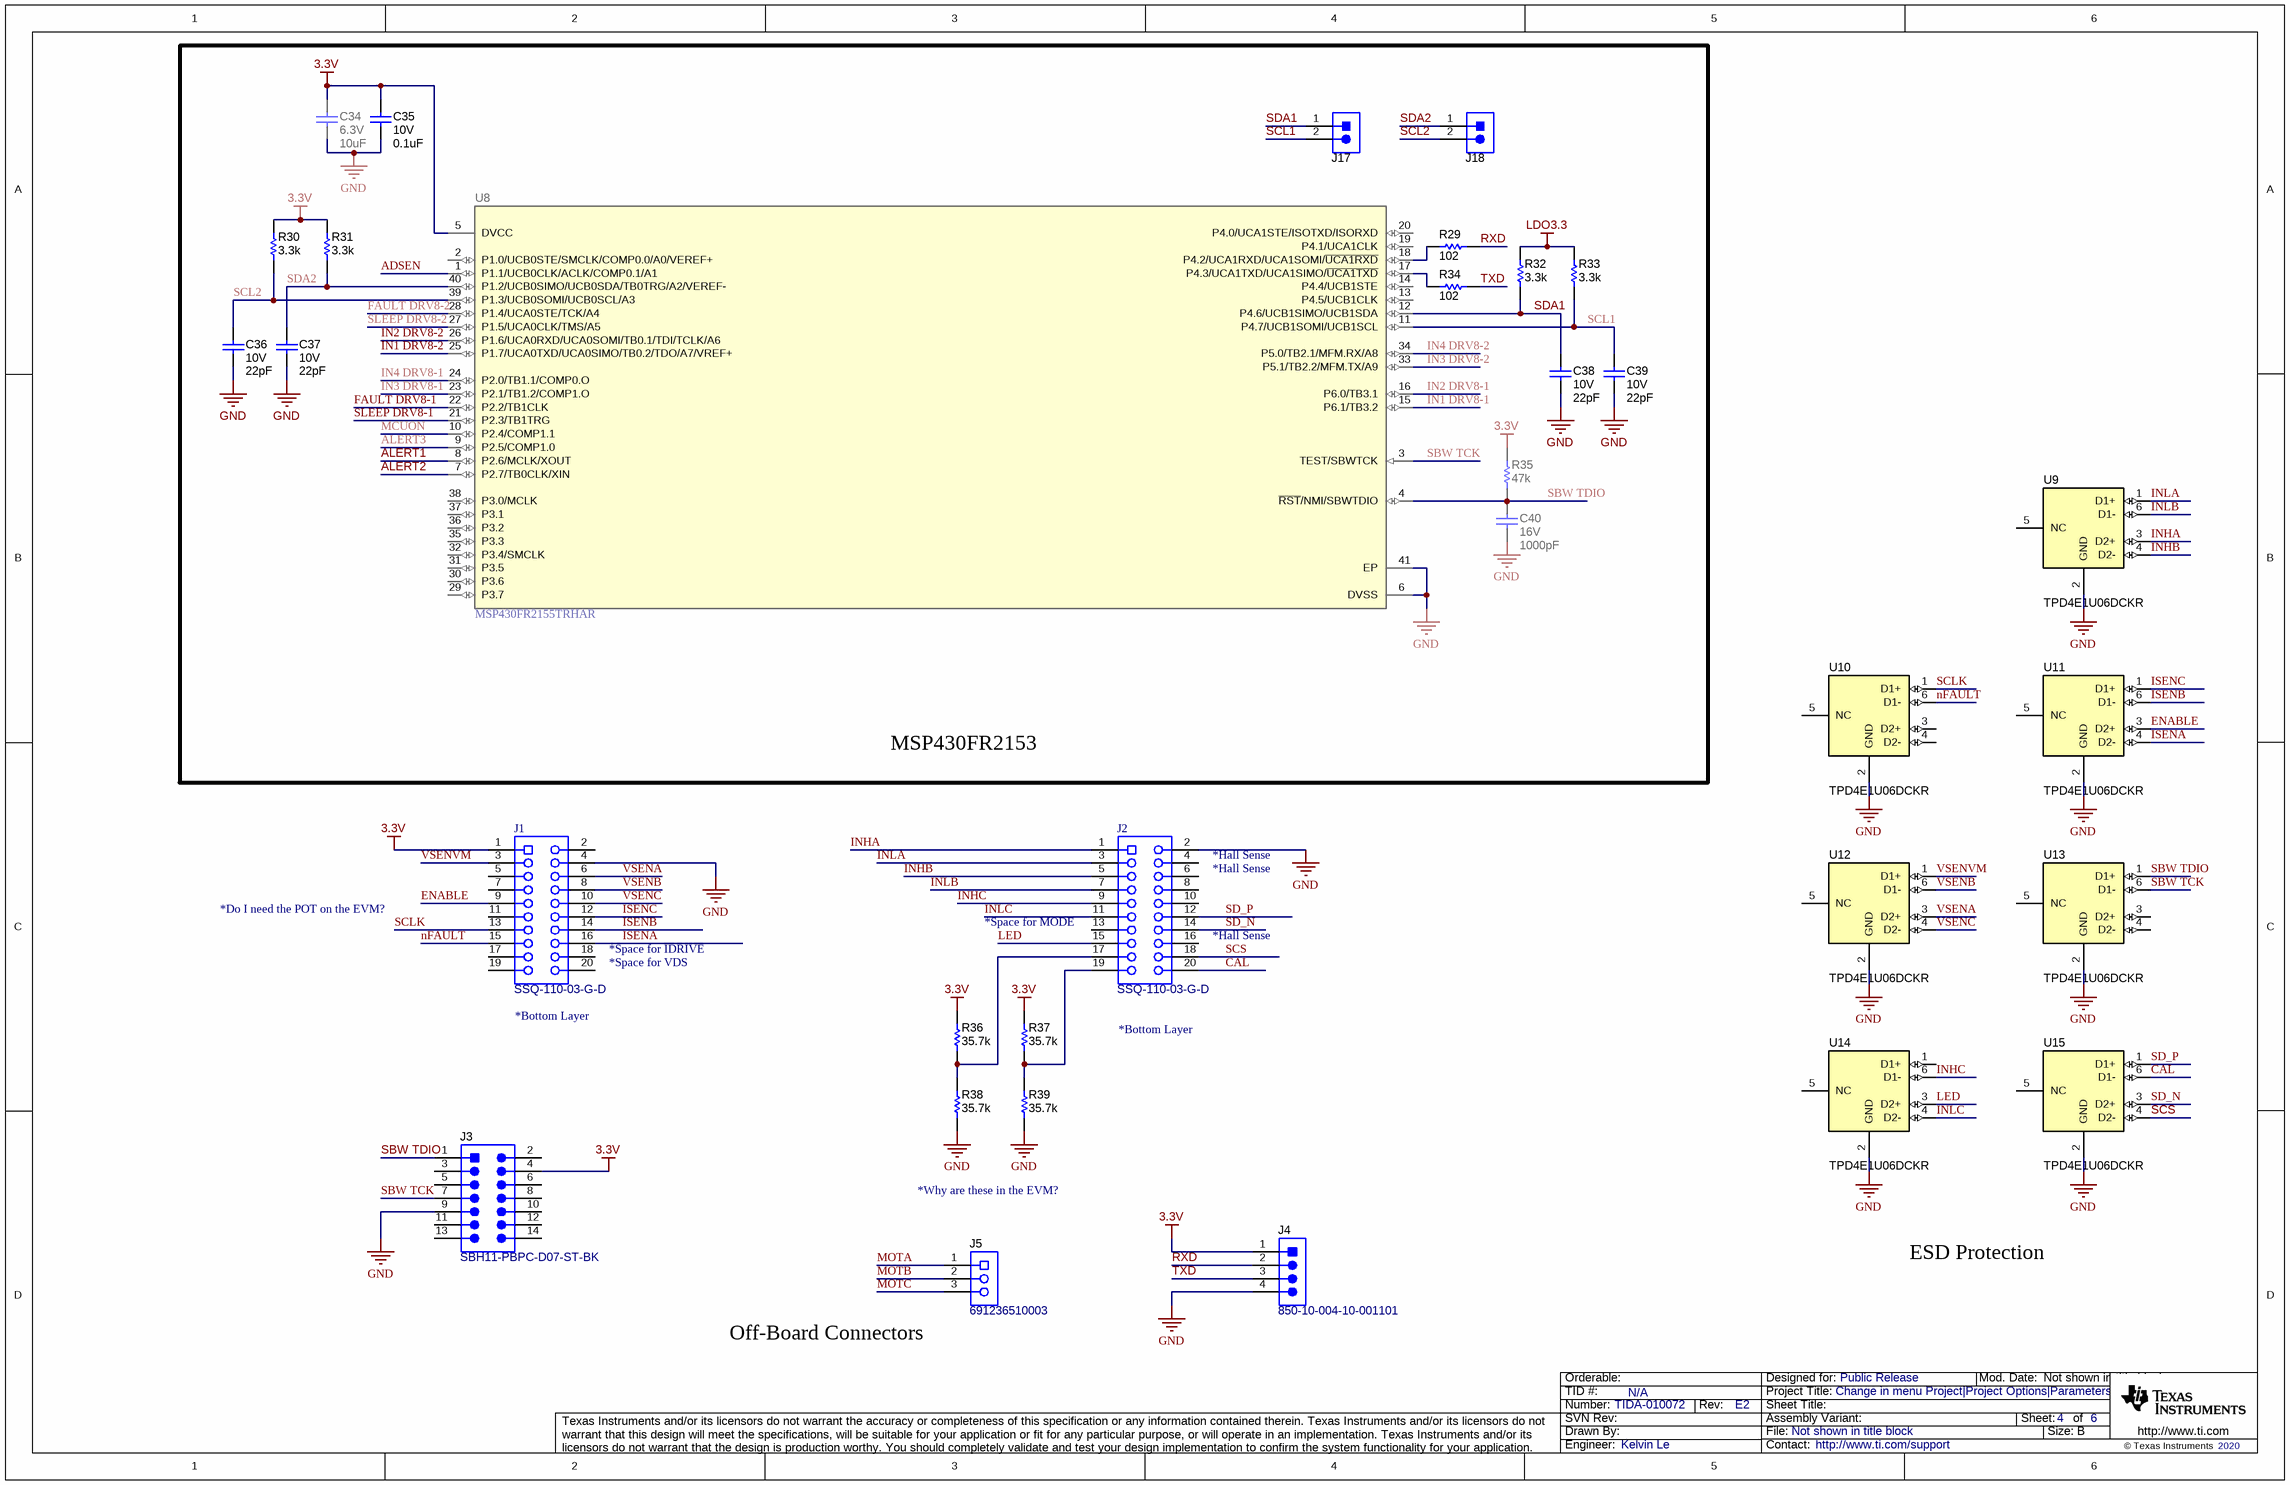
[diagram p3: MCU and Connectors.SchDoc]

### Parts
C34  VDC_V: 6.3V  ValueDisplayed: 10uF  [0603]  (hidden comment: CL10A106MQ8NNNC)
C35  VDC_V: 10V  ValueDisplayed: 0.1uF  [0402]  (hidden comment: 885012105010)
C36  VDC_V: 10V  ValueDisplayed: 22pF  [0402]  (hidden comment: 885012005009)
C37  VDC_V: 10V  ValueDisplayed: 22pF  [0402]  (hidden comment: 885012005009)
C38  VDC_V: 10V  ValueDisplayed: 22pF  [0402]  (hidden comment: 885012005009)
C39  VDC_V: 10V  ValueDisplayed: 22pF  [0402]  (hidden comment: 885012005009)
C40  VDC_V: 16V  ValueDisplayed: 1000pF  [0402]  (hidden comment: GRM155R61C102KA01D)
J1  SSQ-110-03-G-D  [Samtec_SSQ-110-03-x-D]
J2  SSQ-110-03-G-D  [Samtec_SSQ-110-03-x-D]
J3  SBH11-PBPC-D07-ST-BK  [CONN_SBH11-PBPC-D07-ST-BK]
J4  850-10-004-10-001101  [Preci-dip_850-xx-004-10-001101]
J5  691236510003  [Wurth_691236510003]
J17  61300211121  [WURTH_61300211121]  (value not drawn)
J18  61300211121  [WURTH_61300211121]  (value not drawn)
R29  ValueDisplayed: 102  [0402]  (hidden comment: CRCW0402102RFKED)
R30  ValueDisplayed: 3.3k  [0402]  (hidden comment: CRCW04023K30JNED)
R31  ValueDisplayed: 3.3k  [0402]  (hidden comment: CRCW04023K30JNED)
R32  ValueDisplayed: 3.3k  [0402]  (hidden comment: CRCW04023K30JNED)
R33  ValueDisplayed: 3.3k  [0402]  (hidden comment: CRCW04023K30JNED)
R34  ValueDisplayed: 102  [0402]  (hidden comment: CRCW0402102RFKED)
R35  ValueDisplayed: 47k  [0402]  (hidden comment: CRCW040247K0JNED)
R36  ValueDisplayed: 35.7k  [0603]  (hidden comment: CRCW060335K7FKEA)
R37  ValueDisplayed: 35.7k  [0603]  (hidden comment: CRCW060335K7FKEA)
R38  ValueDisplayed: 35.7k  [0603]  (hidden comment: CRCW060335K7FKEA)
R39  ValueDisplayed: 35.7k  [0603]  (hidden comment: CRCW060335K7FKEA)
U8  MSP430FR2155TRHAR  [RHA0040E]
U9  TPD4E1U06DCKR  [DCK0006A_N]
U10  TPD4E1U06DCKR  [DCK0006A_N]
U11  TPD4E1U06DCKR  [DCK0006A_N]
U12  TPD4E1U06DCKR  [DCK0006A_N]
U13  TPD4E1U06DCKR  [DCK0006A_N]
U14  TPD4E1U06DCKR  [DCK0006A_N]
U15  TPD4E1U06DCKR  [DCK0006A_N]

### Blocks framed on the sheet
MSP430FR2153: C34-C40 J17 J18 R29-R35 U8

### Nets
3.3V: C34.1 C35.1 J1.1 J3.4 J4.1 R30.2 R31.2 R35.1 R36.2 R37.2 U8.5(DVCC)
GND: C34.2 C35.2 C36.2 C37.2 C38.2 C39.2 C40.2 J1.4 J2.2 J3.9 J4.4 R38.1 R39.1 U8.6(DVSS) U8.41(EP) U9.2(GND) U10.2(GND) U11.2(GND) U12.2(GND) U13.2(GND) U14.2(GND) U15.2(GND)
LDO3.3: R32.2 R33.2
ADSEN: U8.1(P1.1/UCB0CLK/ACLK/COMP0.1/A1)
ALERT1: U8.8(P2.6/MCLK/XOUT)
ALERT2: U8.7(P2.7/TB0CLK/XIN)
ALERT3: U8.9(P2.5/COMP1.0)
CAL: J2.20 U15.6(D1-)
ENABLE: J1.9 U11.3(D2+)
FAULT DRV8-1: U8.22(P2.2/TB1CLK)
FAULT DRV8-2: U8.28(P1.4/UCA0STE/TCK/A4)
IN1 DRV8-1: U8.15(P6.1/TB3.2)
IN1 DRV8-2: U8.25(P1.7/UCA0TXD/UCA0SIMO/TB0.2/TDO/A7/VREF+)
IN2 DRV8-1: U8.16(P6.0/TB3.1)
IN2 DRV8-2: U8.26(P1.6/UCA0RXD/UCA0SOMI/TB0.1/TDI/TCLK/A6)
IN3 DRV8-1: U8.23(P2.1/TB1.2/COMP1.O)
IN3 DRV8-2: U8.33(P5.1/TB2.2/MFM.TX/A9)
IN4 DRV8-1: U8.24(P2.0/TB1.1/COMP0.O)
IN4 DRV8-2: U8.34(P5.0/TB2.1/MFM.RX/A8)
INHA: J2.1 U9.3(D2+)
INHB: J2.5 U9.4(D2-)
INHC: J2.9 U14.6(D1-)
INLA: J2.3 U9.1(D1+)
INLB: J2.7 U9.6(D1-)
INLC: J2.11 U14.4(D2-)
ISENA: J1.16 U11.4(D2-)
ISENB: J1.14 U11.6(D1-)
ISENC: J1.12 U11.1(D1+)
LED: J2.15 U14.3(D2+)
MCUON: U8.10(P2.4/COMP1.1)
MOTA: J5.1
MOTB: J5.2
MOTC: J5.3
nFAULT: J1.15 U10.6(D1-)
RXD: J4.2 R29.2
SBW TCK: J3.7 U8.3(TEST/SBWTCK) U13.6(D1-)
SBW TDIO: C40.1 J3.1 R35.2 U8.4(~{RST}/NMI/SBWTDIO) U13.1(D1+)
SCL1: C39.1 J17.2 R33.1 U8.11(P4.7/UCB1SOMI/UCB1SCL)
SCL2: C36.1 J18.2 R30.1 U8.39(P1.3/UCB0SOMI/UCB0SCL/A3)
SCLK: J1.13 U10.1(D1+)
SCS: J2.18 U15.4(D2-)
SD_N: J2.14 U15.3(D2+)
SD_P: J2.12 U15.1(D1+)
SDA1: C38.1 J17.1 R32.1 U8.12(P4.6/UCB1SIMO/UCB1SDA)
SDA2: C37.1 J18.1 R31.1 U8.40(P1.2/UCB0SIMO/UCB0SDA/TB0TRG/A2/VEREF-)
SLEEP DRV8-1: U8.21(P2.3/TB1TRG)
SLEEP DRV8-2: U8.27(P1.5/UCA0CLK/TMS/A5)
TXD: J4.3 R34.2
VSENA: J1.6 U12.3(D2+)
VSENB: J1.8 U12.6(D1-)
VSENC: J1.10 U12.4(D2-)
VSENVM: J1.3 U12.1(D1+)
NetJ2_17: J2.17 R36.1 R38.2
NetJ2_19: J2.19 R37.1 R39.2
NetR29_1: R29.1 U8.18(P4.2/UCA1RXD/UCA1SOMI/~{UCA1RXD})
NetR34_1: R34.1 U8.17(P4.3/UCA1TXD/UCA1SIMO/~{UCA1TXD})

Not connected (* = marked no-connect by the designer): J1 2 5 7 11 17 18 19 20; J2 4 6 8 10 13 16; J3 2 3 5 6 8 10 11 12 13 14; U8 2(P1.0/UCB0STE/SMCLK/COMP0.0/A0/VEREF+) 13(P4.5/UCB1CLK) 14(P4.4/UCB1STE) 19(P4.1/UCA1CLK) 20(P4.0/UCA1STE/ISOTXD/ISORXD) 29(P3.7) 30(P3.6) 31(P3.5) 32(P3.4/SMCLK) 35(P3.3) 36(P3.2) 37(P3.1) 38(P3.0/MCLK); U9 5(NC); U10 3(D2+) 4(D2-) 5(NC); U11 5(NC); U12 5(NC); U13 3(D2+) 4(D2-) 5(NC); U14 1(D1+) 5(NC); U15 5(NC)

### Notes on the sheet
- (near J2) *Hall Sense
- *Do I need the POT on the EVM?
- (near J1) *Space for IDRIVE
- (near J1) *Space for VDS
- (near J2) *Space for MODE
- (near J1) *Bottom Layer
- *Bottom Layer
- *Why are these in the EVM?
- ESD Protection
- (near J5) Off-Board Connectors

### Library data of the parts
C34 = CMP-0007107-5: CAP, CERM, 10 uF, 6.3 V, +/- 20%, X5R, 0603; Manufacturer: Samsung Electro-Mechanics; TaMin_C: -55°C; Polarized: N; SizeAreaWB_mm2: 4.68; Value1: Unknown; U/M: EA; Value: 10uF; TaMax_C: 85°C; SizeZ_mm: 1; SizeX_mm: 1.6; SizeY_mm: 0.8; SizeArea_mm2: 1.28; Cap_F: 10µF; AEC Category: Q200
C35 = CMP-0006221-2: as C19 on sheet BLDC Motor Driver and TMP Sensors
C36-C39 = CMP-0064912-2: as C11 on sheet BLDC Motor Driver and TMP Sensors
C40 = CMP-0006589-2: CAP, CERM, 1000 pF, 16 V, +/- 10%, X5R, 0402; Manufacturer: MuRata; TaMin_C: -55°C; Polarized: N; SizeAreaWB_mm2: 3; Value1: Unknown; U/M: EA; Value: 1000pF; TaMax_C: 85°C; SizeZ_mm: 0.6; SizeX_mm: 1; SizeY_mm: 0.5; Cap_F: 1nF; AEC Category: Q200
J1 J2 = CMP-0075613-1: Receptacle, 2.54mm, 10x2, Gold, TH; Manufacturer: Samtec; Pitch_mm: 2.54; Cert_VDE: N; Gender: Female; Cert_CSA: Y; Current_A: 6.3A; Voltage_V: 550V; CT: True; Row_Count: 2; CompType: Socket Strip; CNHeader: False
J3 = CMP-0054695-2: Header (shrouded), 100 mil, 7x2, Gold, TH; Manufacturer: Sullins Connector Solutions; Green_REACh: Incomplete; Green_Lifecycle: Not Set
J4 = CMP-0074999-1: Header, 50mil, 4x1, Gold, TH; Manufacturer: Preci-Dip; CT: False; CNHeader: True
J5 = CMP-0079043-1: Terminal Block, 5.08mm, 3x1, R/A, TH; Manufacturer: Wurth Elektronik; Pitch_mm: 5.08; Cert_VDE: Y; Gender: Female; Voltage_V: 300V; Current_A: 20A; Row_Count: 1
J17 J18 = CMP-0054794-2: Header, 2.54 mm, 2x1, Gold, TH; Manufacturer: Wurth Elektronik; Shrouded: N; Gender: Male; Green_REACh: Passed; Pitch_mm: 2.54; Green_Lifecycle: Active; Row_Count: 1; Cert_UL: Y
R29 R34 = CMP-0025953-3: RES, 102, 1%, 0.063 W, AEC-Q200 Grade 0, 0402; Manufacturer: Vishay-Dale; Power_W: 63mW; TempCo: 100 ppm/C; Value_Code: 102R; Value: 102; EIA_Code: E96; SizeX_mm: 1; SizeY_mm: 0.5; SizeZ_mm: 0.6; Value2: 0.063W; AEC Qualified: Y; VDC_V: 50V; AEC Category: Q200; AEC Grade: 0
R30-R33 = CMP-0026918-5: RES, 3.3 k, 5%, 0.063 W, AEC-Q200 Grade 0, 0402; Manufacturer: Vishay-Dale; Power_W: 63mW; TempCo: 200 ppm/C; Value_Code: 3k30; Value: 3.3k; EIA_Code: E24; SizeX_mm: 1; SizeY_mm: 0.5; SizeZ_mm: 0.6; Value2: 0.063W; AEC Qualified: Y; VDC_V: 50V; AEC Category: Q200; AEC Grade: 0
R35 = CMP-0026935-3: RES, 47 k, 5%, 0.063 W, AEC-Q200 Grade 0, 0402; Manufacturer: Vishay-Dale; Power_W: 63mW; TempCo: 200 ppm/C; Value_Code: 47k0; Value: 47k; EIA_Code: E24; SizeX_mm: 1; SizeY_mm: 0.5; SizeZ_mm: 0.6; Value2: 0.063W; AEC Qualified: Y; VDC_V: 50V; AEC Category: Q200; AEC Grade: 0
R36-R39 = CMP-0022352-4: RES, 35.7 k, 1%, 0.1 W, AEC-Q200 Grade 0, 0603; Manufacturer: Vishay-Dale; Power_W: 100mW; TempCo: 100 ppm/C; Value_Code: 35k7; Value: 35.7k; EIA_Code: E96; SizeX_mm: 1.6; SizeY_mm: 0.8; SizeZ_mm: 1; Value2: 0.1W; SizeArea_mm2: 1.28; AEC Qualified: Y; VDC_V: 75V; AEC Category: Q200; AEC Grade: 0
U8 = CMP-0084068-1: 24MHz 105C ULP Microcontroller With 32 KB FRAM, 4 KB SRAM, 44 IO, 12-bit ADC, RHA0040E (VQFN-40); Manufacturer: Texas Instruments; Alternate PartNumber: MSP430FR2155TRHAT; Rating: Catalog; SizeAreaWB_mm2: 66.4225; SizeArea_mm2: 37.8225; AEC Qualified: N; AEC Category: Q200; SizeZ_mm: 1; SizeY_mm: 6.15; CompType: IC
U9-U15 = CMP-0066606-3: Quad-Channel High-Speed ESD Protection Device, DCK0006A (SOT-SC70-6); Alternate Manufacturer: Texas Instruments; SizeAreaWB_mm2: 9.3; SizeZ_mm: 1.1; SizeX_mm: 2.1; SizeY_mm: 2.0; SizeArea_mm2: 4.2; CompType: IC; AEC Category: Q200; AEC Qualified: N; Rating: Catalog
